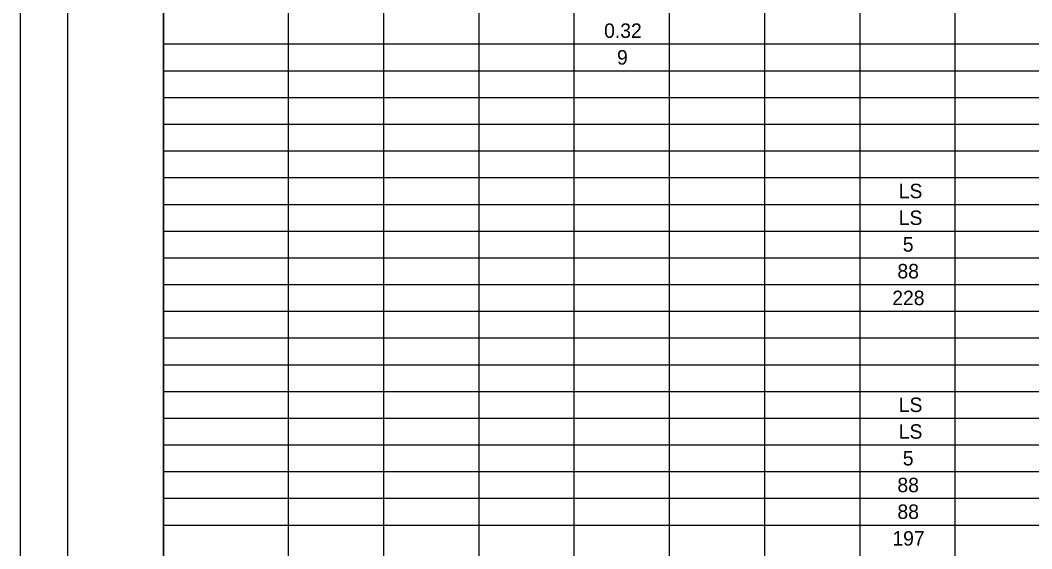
# Model space of a CAD drawing. Extents: x 0 to 44.3, y 0 to 22.
# Drawn here: x 0 to 10.6, y 10.89 to 16.43 of the extents above; entities that cross this region are included whole.
import ezdxf

# ---------------------------------------------------------------- set-up
doc = ezdxf.new("R2010")
doc.units = 0
for name, color, linetype in [('SH_Border', 7, 'Continuous'), ('SH_Cut_Line', 7, 'Continuous'), ('SH_Text', 7, 'Continuous')]:
    doc.layers.add(name, color=color, linetype=linetype)

msp = doc.modelspace()

# ---------------------------------------------------------------- linework, layer by layer
at = {"layer": 'SH_Border'}
for points in [[(0.5, 21.5), (1.5, 21.5), (1.5, 0.5), (0.5, 0.5)], [(1.5, 21.5), (33.5, 21.5), (33.5, 0.5), (1.5, 0.5)]]:
    msp.add_lwpolyline(points, close=True, dxfattribs=at)
at = {"layer": 'SH_Cut_Line'}
msp.add_lwpolyline([(0, 0), (34, 0), (34, 22), (0, 22)], close=True, dxfattribs=at)
at = {"layer": 'SH_Text'}
for p, q in [((1.5, 21.5), (1.5, 0.5)), ((2.809, 20.94), (2.809, 0.5)), ((3.807, 20.94), (3.807, 0.5)), ((4.805, 20.94), (4.805, 0.5)), ((5.803, 20.94), (5.803, 0.5)), ((6.802, 20.94), (6.802, 0.5)), ((7.8, 20.94), (7.8, 0.5)), ((8.798, 20.94), (8.798, 0.5)), ((9.796, 20.94), (9.796, 0.5)), ((1.5, 16.18), (32, 16.18)), ((1.5, 15.9), (32, 15.9)), ((1.5, 15.62), (32, 15.62)), ((1.5, 15.34), (32, 15.34)), ((1.5, 15.06), (32, 15.06)), ((1.5, 14.78), (32, 14.78)), ((1.5, 14.5), (32, 14.5)), ((1.5, 14.22), (32, 14.22)), ((1.5, 13.94), (32, 13.94)), ((1.5, 13.66), (32, 13.66)), ((1.5, 13.38), (32, 13.38)), ((1.5, 13.1), (32, 13.1)), ((1.5, 12.82), (32, 12.82)), ((1.5, 12.54), (32, 12.54)), ((1.5, 12.26), (32, 12.26)), ((1.5, 11.98), (32, 11.98)), ((1.5, 11.7), (32, 11.7)), ((1.5, 11.42), (32, 11.42)), ((1.5, 11.14), (32, 11.14))]:
    msp.add_line(p, q, dxfattribs=at)

# ---------------------------------------------------------------- texts
for s, height, p in [('0.32', 0.1515, (6.119, 16.244)), ('9', 0.152, (6.254, 15.964)), ('LS', 0.1515, (9.207, 14.564)), ('LS', 0.1515, (9.207, 14.284)), ('5', 0.152, (9.249, 14.004)), ('88', 0.1515, (9.193, 13.724)), ('228', 0.1515, (9.139, 13.444)), ('LS', 0.1515, (9.207, 12.324)), ('LS', 0.1515, (9.207, 12.044)), ('5', 0.152, (9.249, 11.764)), ('88', 0.1515, (9.193, 11.484)), ('88', 0.1515, (9.193, 11.204)), ('197', 0.1515, (9.14, 10.924))]:
    msp.add_text(s, height=height, dxfattribs=at).set_placement(p)

doc.saveas('drawing.dxf')
